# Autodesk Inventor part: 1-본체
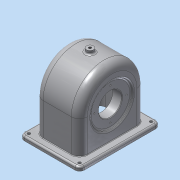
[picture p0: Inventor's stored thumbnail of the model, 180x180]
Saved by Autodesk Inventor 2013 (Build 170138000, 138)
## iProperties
Created: 2016-01
Part Number: 1-본체
Material: 알루미늄 6061
Document SubType Name: Modeling
Designer: dgall
Density: 2.71 g/cm^3
Mass: 809.754 g
Surface Area: 999.207 cm^2
Volume: 298.802 cm^3
Author: dgall
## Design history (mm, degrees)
sketch "스케치1"
  geometry: L1 (-52, 70)-(52, 70); L2 (52, 70)-(52, -70); L3 (52, -70)-(-52, -70); L4 (-52, -70)-(-52, 70); 3 further points
  constraints: 8 end point, 2 midpoint, 2 parallel, 1 horizontal, 1 horizontal alignment, 1 perpendicular, 1 vertical alignment
  dimensions: "d0" = 104 distance of L1.start L1.end; "d2" = 140 distance of L1.end L2.end
extrude "돌출1" new body sketch "스케치1" distance "d3" = 7; taper "d4" = 0 deg
node "작업 평면1"
sketch "스케치2"
  geometry: L1 (0, 0)-(0, 140) reference; L2 (-7, 140)-(0, 140) reference; L3 (0, 140)-(0, 0) reference; L4 (0, 0)-(-7, 0) reference; L5 (-7, 0)-(-7, 140) reference; L6 (-64, 13)-(-7, 13); L7 (-64, 127)-(-7, 127); L8 (0, 19)-(-64, 19); L9 (-64, 121)-(0, 121); A1 r 57 centre (-64, 70) between (-64, 127) and (-64, 13); A2 r 51 centre (-64, 70) between (-64, 121) and (-64, 19); 1 further point
  constraints: 8 end point, 4 point on circle, 4 point on line, 2 centre point, 2 perpendicular, 2 tangent, 1 horizontal alignment, 1 parallel
  dimensions: "d5" = 57 radius of A1; "d6" = 64 distance from line of L1 A1.centre; "d7" = 6 distance between parallel lines of L7 L9; "d8" = 6 radial gap between concentric circles of A1 A2; "d9" = 6 distance between parallel lines of L6 L8
  node "절단 모서리 투영1"
extrude "돌출2" join sketch "스케치2" stored distance "d10" = 77; taper "d11" = 0 deg
extrude "돌출3" cut sketch "스케치2" stored distance "d12" = 67; taper "d13" = 0 deg
node "작업 평면2"
node "작업 평면3"
node "작업 평면4"
node "작업 평면5"
node "작업 평면7"
node "작업 평면8"
node "작업 평면9"
node "작업 평면10"
sketch "스케치10"
  geometry: L1 (0, 0)-(0, 140) reference; C1 r 31 at (60, 70); 2 further points
  constraints: 1 centre point, 1 horizontal alignment, 1 midpoint
  dimensions: "d53" = 62 diameter of C1; "d54" = 60 distance from line of L1 C1.centre
extrude "돌출8" join sketch "스케치10" distance "d55" = 10; taper "d56" = 0 deg
node "작업 평면11"
sketch "스케치11"
  geometry: L1 (77, 57)-(77, -57) reference; L2 (77, -57)-(0, -57) reference; L3 (0, -57)-(0, -27) reference; L4 (0, -27)-(-10, -27) reference; L5 (-10, -27)-(-10, 35) reference; L6 (-10, 35)-(0, 35) reference; L7 (0, 35)-(0, 57) reference; L8 (0, 57)-(-13.5, 57) reference; L9 (-13.5, 57)-(-13.5, 64) reference; L10 (-13.5, 64)-(5, 64) reference; L11 (5, 64)-(5, -51) reference; L12 (5, -51)-(72, -51) reference; L13 (72, -51)-(72, 64) reference; L14 (72, 64)-(90.5, 64) reference; L15 (90.5, 64)-(90.5, 57) reference; L16 (90.5, 57)-(77, 57) reference; L17 (-10, 4)-(77, 4); L18 (77, -39.943)-(58, -24); L19 (58, -24)-(58, 4); 1 further point
  constraints: 6 end point, 3 point on line, 2 perpendicular, 1 midpoint
  dimensions: "d57" = 50 deg angle of L19 L18; "d58" = 56 diameter of L18.end L17; "d60" = 19 distance between parallel lines of L1 L19
revolve "회전3" sketch "스케치11" stored, may be unused: angle "d61" = 90 deg
node "작업 평면12"
node "작업 평면13"
sketch "스케치12"
  geometry: L1 (-7, 13)-(-64, 13) reference; L2 (-64, 127)-(-7, 127) reference; L3 (-7, 127)-(-7, 140) reference; L4 (-7, 140)-(0, 140) reference; L5 (0, 140)-(0, 121) reference; L6 (0, 121)-(-64, 121) reference; L7 (-64, 19)-(0, 19) reference; L8 (0, 19)-(0, 0) reference; L9 (0, 0)-(-7, 0) reference; L10 (-7, 0)-(-7, 13) reference; C1 r 28 at (-60, 70); A1 r 57 centre (-64, 70) between (-64, 127) and (-64, 13) reference; A2 r 51 centre (-64, 70) between (-64, 121) and (-64, 19) reference; 1 further point
  constraints: 1 centre point, 1 horizontal alignment
  dimensions: "d64" = 56 diameter of C1; "d66" = 60 distance from line of L5 C1.centre
extrude "돌출9" join sketch "스케치12" stored distance "d67" = 10; taper "d68" = 40 deg
node "작업 평면14"
sketch "스케치13"
  geometry: L1 (5, 64)-(5, -51) reference; L2 (5, -51)-(72, -51) reference; L3 (72, -51)-(72, -35.747) reference; L4 (72, -35.747)-(58, -24) reference; L5 (58, -24)-(58, 32) reference; L6 (58, 32)-(72, 43.747) reference; L7 (72, 43.747)-(72, 64) reference; L8 (72, 64)-(90.5, 64) reference; L9 (90.5, 64)-(90.5, 57) reference; L10 (90.5, 57)-(77, 57) reference; L11 (77, 57)-(77, 47.943) reference; L12 (77, 47.943)-(74, 45.426) reference; L13 (74, 45.426)-(74, -37.426) reference; L14 (74, -37.426)-(77, -39.943) reference; L15 (77, -39.943)-(77, -57) reference; L16 (77, -57)-(0, -57) reference; L17 (0, -57)-(0, -27) reference; L18 (0, -27)-(-10, -27) reference; L19 (-10, -27)-(-10, 35) reference; L20 (-10, 35)-(0, 35) reference; L21 (0, 35)-(0, 57) reference; L22 (0, 57)-(-13.5, 57) reference; L23 (-13.5, 57)-(-13.5, 64) reference; L24 (-13.5, 64)-(5, 64) reference; L25 (77, -33.416)-(58, -17.473); L26 (77, 47.943)-(77, -39.943) reference; L27 (77, 4)-(-10, 4); L28 (5, 64)-(72, 64) reference; L29 (77, -33.416)-(77, -39.943); L30 (58, -24)-(77, -39.943); L31 (58, -24)-(58, -17.473); 1 further point
  constraints: 10 end point, 2 midpoint, 2 perpendicular, 2 point on line, 1 collinear, 1 parallel
  dimensions: "d69" = 5 distance between parallel lines of L14 L25; "d70" = 60 distance between parallel lines of L28 L27
revolve "회전4" sketch "스케치13" stored, may be unused: angle "d71" = 90 deg
sketch "스케치14"
  geometry: C1 r 31 at (0, 0) reference; C2 r 20 at (0, 0); 1 further point
  constraints: 1 centre point, 1 coincident
  dimensions: "d72" = 40 diameter of C2
extrude "돌출10" cut sketch "스케치14" stored distance "d73" = 10; taper "d74" = 0 deg
sketch "스케치15"
  geometry: C1 r 20 at (0, 0) reference; C2 r 31 at (0, 0) reference; A1 r 24 centre (0, 0) between (24, 0) and (0, 24); 3 further points
  constraints: 4 point on circle, 2 horizontal alignment, 2 vertical alignment, 1 centre point, 1 coincident
  dimensions: "d75" = 48 diameter of A1
hole "구멍1" sketch "스케치15" at (24, 0), (0, 24), (0, -24), (-24, 0) diameter "d76" = 2.459; stored, may be unused: countersink angle "d80" = 90 deg, drill point angle "d82" = 118 deg; dims "d77" = 6, "d78" = 4, "d79" = 2, "d81" = 8
sketch "스케치16"
  geometry: C1 r 20 at (0, 0) reference; C2 r 34.899 at (0, 0) reference; A1 r 28 centre (0, 0) between (-28, 0) and (28, 0); 3 further points
  constraints: 4 point on circle, 2 horizontal alignment, 2 vertical alignment, 1 centre point, 1 coincident
  dimensions: "d83" = 56 diameter of A1
hole "구멍2" sketch "스케치16" at (-28, 0), (28, 0), (0, -28), (0, 28) diameter "d84" = 2.459; stored, may be unused: countersink angle "d88" = 90 deg, drill point angle "d90" = 118 deg; dims "d85" = 7, "d86" = 4, "d87" = 2, "d89" = 9
node "작업 평면15"
sketch "스케치17"
  geometry: C1 r 6 at (0, 0); 1 further point
  constraints: 1 centre point, 1 coincident
  dimensions: "d92" = 12 diameter of C1
extrude "돌출11" join sketch "스케치17" stored distance "d93" = 10; taper "d94" = 0 deg
hole "구멍3" diameter "d97" = 4.459; stored, may be unused: countersink angle "d101" = 90 deg, drill point angle "d103" = 118 deg; dims "d95" = 10, "d96" = 10, "d98" = 7, "d99" = 4, "d100" = 2, "d102" = 9
fillet "모깎기1" dims "d104" = 9
fillet "모깎기2" dims "d105" = 14
fillet "모깎기3" dims "d106" = 3
chamfer "모따기1" distance "d107" = 1; stored, may be unused: second distance "d108" = 2, angle "d109" = 45 deg
fillet "모깎기4" dims "d110" = 8
sketch "스케치18"
  geometry: C1 r 2.5 at (-44, 62); C2 r 2.5 at (44, 62); C3 r 2.5 at (44, -62); C4 r 2.5 at (-44, -62); A1 r 8 centre (-44, -62) between (-52, -62) and (-44, -70) reference; A2 r 8 centre (44, -62) between (44, -70) and (52, -62) reference; A3 r 8 centre (44, 62) between (52, 62) and (44, 70) reference; A4 r 8 centre (-44, 62) between (-44, 70) and (-52, 62) reference; 1 further point
  constraints: 4 centre point, 4 coincident, 3 equal radius
  dimensions: "d111" = 5 diameter of C1
extrude "돌출12" cut sketch "스케치18" stored distance "d113" = 10; taper "d114" = 0 deg
fillet "모깎기5" dims "d115" = 3
fillet "모깎기6" dims "d116" = 1
sketch "스케치19"
  geometry: L1 (-19.5, 64)-(68.5, 64) reference; L2 (63, 0)-(63, 56) reference; 2 further points
  constraints: 1 other
  dimensions: "d117" = 30 distance from line of L1 point (24.5, 34); "d118" = 38.5 distance from line of L2 point (24.5, 34)
feature "엠보싱1" sketch "스케치19" dims "d7" = 6, "d119" = 0.5, "d120" = 0
fillet "모깎기7" dims "d121" = 3
node "솔리드1"
node "절단 모서리 투영4"
node "절단 모서리 투영5"
node "절단 모서리 투영6"
other parameters: "d27" = -19, "d46" = -3, "d47" = -19, "d48" = -3, "d49" = -19, "d62" = -3, "d63" = -19, "d91" = -127
